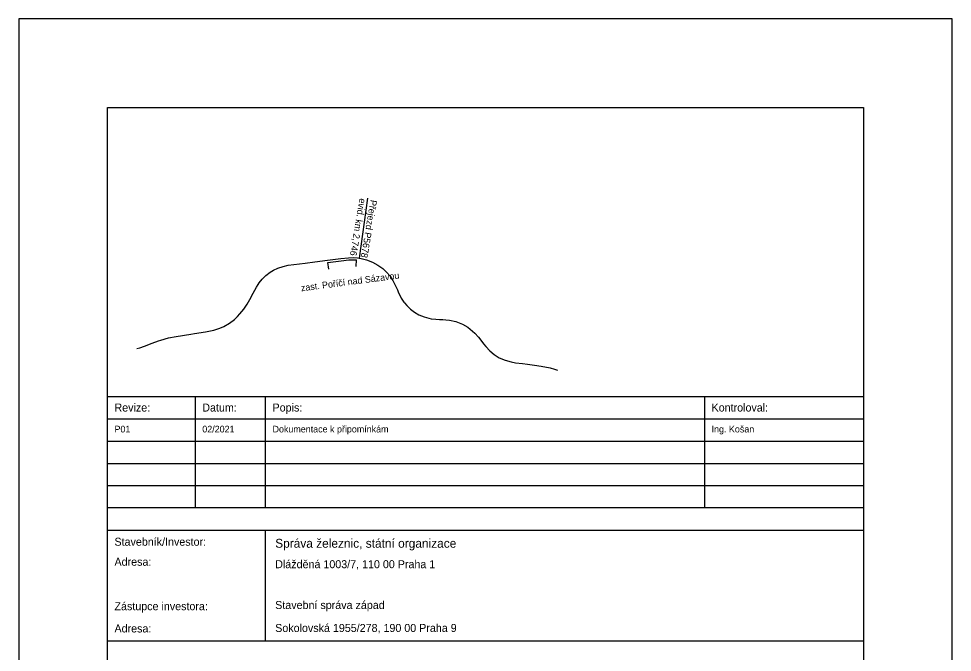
# Model space of a CAD drawing. Extents: x 25 to 46, y -50 to -20.3.
# Drawn here: x 25 to 46, y -34.55 to -20.3 of the extents above; entities that cross this region are included whole.
import ezdxf

# ---------------------------------------------------------------- set-up
doc = ezdxf.new("R2010")
doc.units = 0
for name, color, linetype in [('_popis', 7, 'Continuous'), ('Rozpiska_pole_1', 7, 'Continuous'), ('Rozpiska_pole_4', 7, 'Continuous'), ('Rozpiska_pole_5', 7, 'Continuous'), ('Rozpiska_pole_6', 7, 'Continuous')]:
    doc.layers.add(name, color=color, linetype=linetype)

msp = doc.modelspace()

# ---------------------------------------------------------------- linework, layer by layer
msp.add_lwpolyline([(25, -50), (46, -50), (46, -20.3), (25, -20.3)], close=True)
at = {"layer": '_popis'}
for p, q in [((32.844, -24.336), (32.66, -25.683)), ((31.975, -25.93), (31.956, -25.781)), ((32.588, -25.876), (32.597, -25.727))]:
    msp.add_line(p, q, dxfattribs=at)
for points in [[(27.658, -27.715), (27.724, -27.699), (27.831, -27.665), (28.005, -27.601), (28.148, -27.547), (28.2, -27.529), (28.371, -27.481), (28.542, -27.449), (28.872, -27.394), (28.957, -27.38), (29.205, -27.339), (29.388, -27.304), (29.435, -27.292), (29.528, -27.261), (29.615, -27.223), (29.745, -27.148), (29.857, -27.062), (29.924, -26.997), (29.976, -26.941), (30.064, -26.831), (30.142, -26.717), (30.202, -26.616), (30.277, -26.473), (30.349, -26.336), (30.387, -26.275), (30.41, -26.241), (30.476, -26.159), (30.558, -26.079), (30.658, -26.003), (30.732, -25.958), (30.83, -25.911), (30.947, -25.871), (31.061, -25.847), (31.187, -25.829), (31.444, -25.796), (31.66, -25.769), (31.947, -25.732), (32.244, -25.694), (32.422, -25.675), (32.526, -25.672), (32.624, -25.678), (32.66, -25.683), (32.706, -25.691), (32.821, -25.72), (32.959, -25.773), (33.081, -25.841), (33.188, -25.92), (33.271, -25.998), (33.352, -26.093), (33.416, -26.188), (33.471, -26.292), (33.518, -26.399), (33.538, -26.444), (33.606, -26.583), (33.664, -26.672), (33.677, -26.69), (33.731, -26.753), (33.813, -26.833), (33.903, -26.901), (34.002, -26.959), (34.117, -27.007), (34.276, -27.048), (34.385, -27.06), (34.465, -27.064), (34.537, -27.067), (34.609, -27.071), (34.69, -27.079), (34.833, -27.11), (34.984, -27.169), (35.103, -27.238), (35.257, -27.37), (35.341, -27.466), (35.417, -27.561), (35.457, -27.613), (35.508, -27.674), (35.598, -27.771), (35.694, -27.851), (35.811, -27.925), (35.944, -27.982), (36.078, -28.019), (36.175, -28.036), (36.332, -28.058), (36.445, -28.073), (36.603, -28.094), (36.752, -28.114), (36.951, -28.153), (37.05, -28.182), (37.097, -28.198), (37.123, -28.207)], [(31.956, -25.781), (32.25, -25.744), (32.425, -25.725), (32.525, -25.722), (32.597, -25.727)]]:
    msp.add_lwpolyline(points, dxfattribs=at)
at = {"layer": 'Rozpiska_pole_1'}
msp.add_lwpolyline([(27, -22.3), (44, -22.3), (44, -48.3), (27, -48.3)], close=True, dxfattribs=at)
at = {"layer": 'Rozpiska_pole_4'}
for p, q in [((28.975, -31.3), (28.975, -28.8)), ((30.555, -31.3), (30.555, -28.8)), ((40.43, -31.3), (40.43, -28.8)), ((27, -29.3), (44, -29.3)), ((27, -29.8), (44, -29.8)), ((27, -30.3), (44, -30.3)), ((27, -30.8), (44, -30.8))]:
    msp.add_line(p, q, dxfattribs=at)
msp.add_lwpolyline([(27, -28.8), (44, -28.8), (44, -31.3), (27, -31.3)], close=True, dxfattribs=at)
at = {"layer": 'Rozpiska_pole_5'}
msp.add_line((30.555, -34.3), (30.555, -31.8), dxfattribs=at)
msp.add_lwpolyline([(27, -31.8), (44, -31.8), (44, -34.3), (27, -34.3)], close=True, dxfattribs=at)

# ---------------------------------------------------------------- texts
at = {"layer": '_popis'}
for s, rotation, p in [('evid. km 2,746', 260.4567, (32.666, -24.333)), ('Přejezd P5678', 260.4567, (32.913, -24.367)), ('zast. Poříčí nad Sázavou', 7.4528, (31.358, -26.433))]:
    msp.add_text(s, height=0.15, rotation=rotation, dxfattribs=at).set_placement(p)
at = {"layer": 'Rozpiska_pole_4'}
for s, height, p in [('Revize:', 0.18, (27.155, -29.135)), ('Datum:', 0.18, (29.13, -29.135)), ('Popis:', 0.18, (30.71, -29.135)), ('Kontroloval:', 0.18, (40.585, -29.135)), ('P01', 0.15, (27.155, -29.605)), ('02/2021', 0.15, (29.13, -29.605)), ('Dokumentace k připomínkám', 0.15, (30.71, -29.605)), ('Ing. Košan', 0.15, (40.585, -29.605))]:
    msp.add_text(s, height=height, dxfattribs=at).set_placement(p)
at = {"layer": 'Rozpiska_pole_5'}
for s, height, p in [('Stavebník/Investor:', 0.18, (27.155, -32.153)), ('Správa železnic, státní organizace', 0.2, (30.77, -32.198)), ('Adresa:', 0.18, (27.155, -32.603)), ('Zástupce investora:', 0.18, (27.155, -33.603)), ('Adresa:', 0.18, (27.155, -34.103))]:
    msp.add_text(s, height=height, dxfattribs=at).set_placement(p)
at = {"layer": 'Rozpiska_pole_6'}
for s, p in [('Dlážděná 1003/7, 110 00 Praha 1', (30.77, -32.658)), ('Stavební správa západ', (30.77, -33.576)), ('Sokolovská 1955/278, 190 00 Praha 9', (30.77, -34.092))]:
    msp.add_text(s, height=0.18, dxfattribs=at).set_placement(p)

doc.saveas('drawing.dxf')
